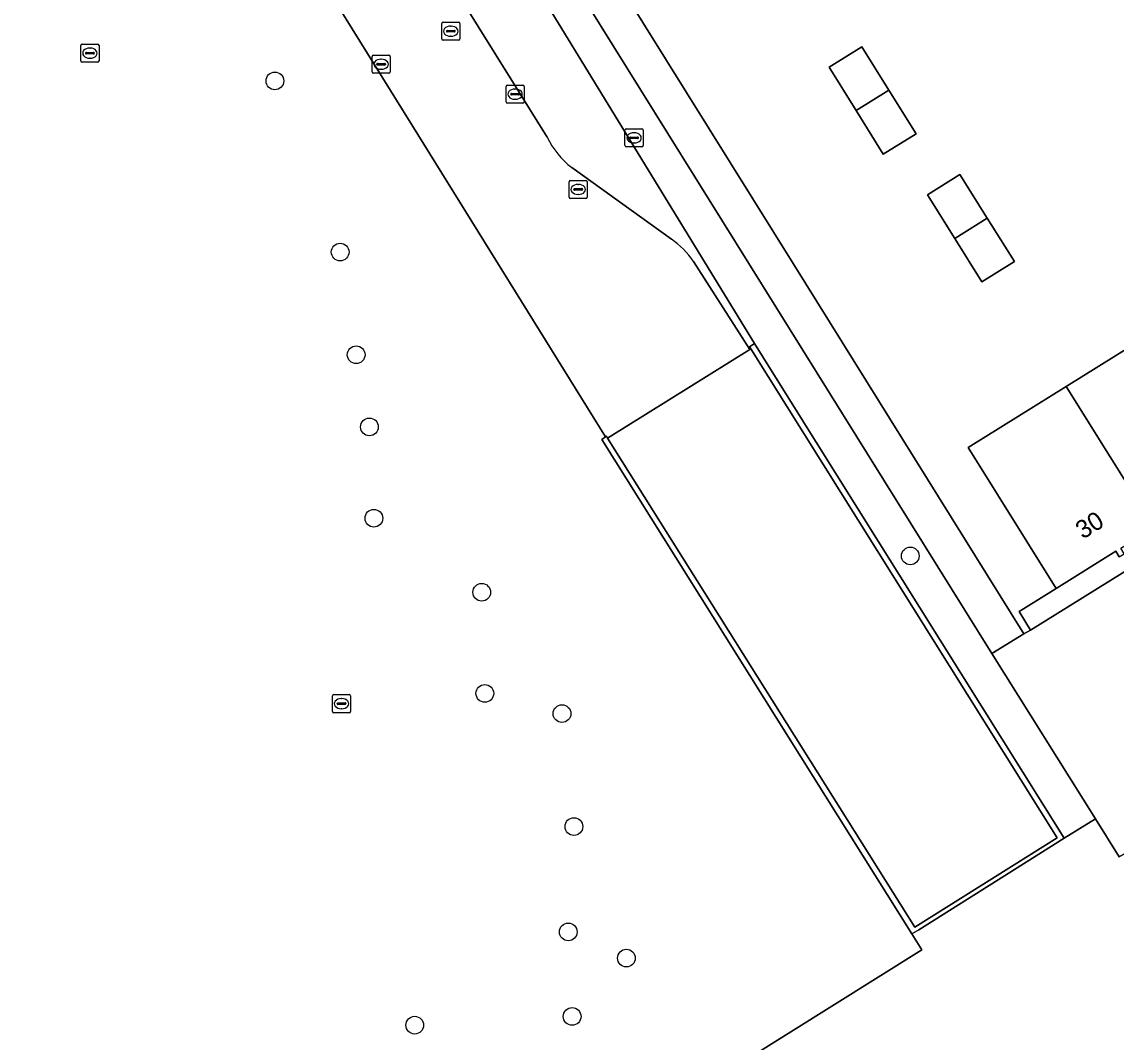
# Model space of a CAD drawing. Extents: x 159279 to 160377, y 384531 to 385888.
# Drawn here: x 159404.1 to 159464.5, y 385373.4 to 385429.8 of the extents above; entities that cross this region are included whole.
import ezdxf

# ---------------------------------------------------------------- set-up
doc = ezdxf.new("R2010")
doc.units = 0
for name, color, linetype in [('IMGEO_Boom', 7, 'Continuous'), ('IMGEO_Erf', 7, 'Continuous'), ('IMGEO_Groenvoorziening', 7, 'Continuous'), ('IMGEO_Kolk', 7, 'Continuous'), ('IMGEO_Muur', 7, 'Continuous'), ('IMGEO_Pand', 7, 'Continuous'), ('IMGEO_Pand_nummerreeks', 7, 'Continuous'), ('IMGEO_Rijbaan_lokaal_gesloten', 7, 'Continuous'), ('IMGEO_Rijbaan_lokaal_open', 7, 'Continuous'), ('IMGEO_Rioolput', 7, 'Continuous'), ('IMGEO_Voetgangersgebied_open', 7, 'Continuous')]:
    doc.layers.add(name, color=color, linetype=linetype)

msp = doc.modelspace()

# ---------------------------------------------------------------- linework, layer by layer
at = {"layer": 'IMGEO_Boom'}
for centre in [(159418.043, 385426.531), (159421.652, 385417.071), (159422.537, 385411.392), (159423.269, 385407.403), (159423.515, 385402.353), (159453.16, 385400.269), (159429.475, 385398.261), (159429.647, 385392.667), (159433.911, 385391.553), (159434.569, 385385.306), (159434.26, 385379.483), (159437.468, 385378.033), (159434.472, 385374.809), (159425.773, 385374.327)]:
    msp.add_circle(centre, 0.489, dxfattribs=at)
at = {"layer": 'IMGEO_Erf'}
for points in [[(159432.397, 385439.388), (159445.622, 385418.149), (159446.687, 385416.44), (159459.434, 385395.969), (159459.81, 385396.164), (159459.179, 385397.202), (159459.413, 385397.348), (159461.218, 385398.473), (159456.364, 385406.265), (159461.772, 385409.641), (159467.18, 385413.017), (159472.589, 385416.393), (159475.103, 385417.962), (159477.999, 385419.765), (159483.412, 385423.134), (159488.824, 385426.503), (159491.783, 385421.784), (159493.723, 385418.733), (159495.539, 385419.868), (159483.57, 385439.063)], [(159464.706, 385400.218), (159464.512, 385400.532), (159461.218, 385398.473), (159459.413, 385397.348), (159459.179, 385397.202), (159459.81, 385396.164), (159496.527, 385419.019)]]:
    msp.add_lwpolyline(points, dxfattribs=at)
for points in [[(159451.973, 385426.016), (159453.476, 385423.609), (159451.657, 385422.483), (159450.162, 385424.891), (159448.666, 385427.298), (159450.471, 385428.423)], [(159457.408, 385418.95), (159458.925, 385416.548), (159457.108, 385415.416), (159455.616, 385417.818), (159454.115, 385420.235), (159455.891, 385421.352)]]:
    msp.add_lwpolyline(points, close=True, dxfattribs=at)
at = {"layer": 'IMGEO_Groenvoorziening'}
for points in [[(159453.246, 385379.369), (159436.106, 385406.715), (159436.318, 385406.853), (159425.611, 385424.096), (159406.852, 385454.306)], [(159441.177, 385416.554), (159444.284, 385411.674), (159444.345, 385411.717), (159444.272, 385411.833), (159444.546, 385412.006), (159427.827, 385439.37), (159429.31, 385440.411)], [(159423.605, 385438.656), (159433.086, 385423.419)], [(159434.452, 385421.739), (159439.954, 385417.78)], [(159366.933, 385321.453), (159368.853, 385322.693), (159367.822, 385324.378), (159372.867, 385327.564), (159374.917, 385324.392), (159380.243, 385327.744), (159378.085, 385331.09), (159453.794, 385378.488), (159453.246, 385379.369)]]:
    msp.add_lwpolyline(points, dxfattribs=at)
msp.add_lwpolyline([(159429.31, 385440.411), (159427.827, 385439.37), (159444.546, 385412.006), (159446.812, 385408.385), (159461.661, 385384.66), (159463.396, 385385.729), (159457.667, 385394.881)], close=True, dxfattribs=at)
for centre, radius, start, end in [((159437.559, 385425.661), 5.003, 206.61733, 231.61146), ((159437.134, 385413.744), 4.924, 34.80227, 55.05735)]:
    msp.add_arc(centre, radius, start, end, dxfattribs=at)
at = {"layer": 'IMGEO_Kolk'}
for p, q in [((159423.414, 385427.027), (159423.414, 385427.879)), ((159423.489, 385427.953), (159424.341, 385427.953)), ((159423.902, 385427.733), (159423.927, 385427.733)), ((159424.415, 385427.879), (159424.415, 385427.027)), ((159423.673, 385427.447), (159423.673, 385427.459)), ((159424.111, 385427.41), (159423.713, 385427.41)), ((159423.716, 385427.496), (159424.114, 385427.496)), ((159423.925, 385427.173), (159423.9, 385427.173)), ((159424.157, 385427.459), (159424.157, 385427.447)), ((159424.341, 385426.953), (159423.489, 385426.953)), ((159430.817, 385425.374), (159430.817, 385426.226)), ((159430.892, 385426.3), (159431.744, 385426.3)), ((159431.076, 385425.794), (159431.076, 385425.806)), ((159431.119, 385425.843), (159431.517, 385425.843)), ((159431.305, 385426.08), (159431.33, 385426.08)), ((159431.56, 385425.806), (159431.56, 385425.794)), ((159431.818, 385426.226), (159431.818, 385425.374)), ((159431.744, 385425.3), (159430.892, 385425.3)), ((159431.514, 385425.757), (159431.116, 385425.757)), ((159431.328, 385425.52), (159431.303, 385425.52)), ((159437.392, 385422.958), (159437.392, 385423.81)), ((159437.467, 385423.884), (159438.319, 385423.884)), ((159437.651, 385423.378), (159437.651, 385423.39)), ((159437.694, 385423.427), (159438.092, 385423.427)), ((159437.88, 385423.664), (159437.905, 385423.664)), ((159438.135, 385423.39), (159438.135, 385423.378)), ((159438.393, 385423.81), (159438.393, 385422.958)), ((159438.319, 385422.884), (159437.467, 385422.884)), ((159438.089, 385423.341), (159437.691, 385423.341)), ((159437.903, 385423.104), (159437.878, 385423.104))]:
    msp.add_line(p, q, dxfattribs=at)
for points in [[(159423.414, 385427.027), (159423.414, 385427.879)], [(159423.489, 385427.953), (159424.341, 385427.953)], [(159424.415, 385427.879), (159424.415, 385427.027)], [(159424.341, 385426.953), (159423.489, 385426.953)], [(159430.817, 385425.374), (159430.817, 385426.226)], [(159430.892, 385426.3), (159431.744, 385426.3)], [(159431.818, 385426.226), (159431.818, 385425.374)], [(159431.744, 385425.3), (159430.892, 385425.3)], [(159437.392, 385422.958), (159437.392, 385423.81)], [(159437.467, 385423.884), (159438.319, 385423.884)], [(159438.393, 385423.81), (159438.393, 385422.958)], [(159438.319, 385422.884), (159437.467, 385422.884)]]:
    msp.add_lwpolyline(points, dxfattribs=at)
for centre, radius, start, end in [((159423.491, 385427.877), 0.0765, 91.55205, 178.44795), ((159423.491, 385427.877), 0.0765, 91.55205, 178.44795), ((159424.339, 385427.877), 0.0765, 1.55205, 88.44795), ((159424.339, 385427.877), 0.0765, 1.55205, 88.44795), ((159423.491, 385427.029), 0.0765, 181.55205, 268.44795), ((159423.491, 385427.029), 0.0765, 181.55205, 268.44795), ((159423.713, 385427.456), 0.0403, 85.87752, 175.75265), ((159423.71, 385427.446), 0.0366, 178.93798, 274.71019), ((159424.114, 385427.453), 0.043, 264.86636, 352.45326), ((159424.118, 385427.458), 0.0386, 1.73085, 96.63898), ((159424.339, 385427.029), 0.0765, 271.55205, 358.44795), ((159424.339, 385427.029), 0.0765, 271.55205, 358.44795), ((159430.894, 385426.224), 0.0765, 91.55205, 178.44795), ((159430.894, 385426.224), 0.0765, 91.55205, 178.44795), ((159431.116, 385425.803), 0.0403, 85.87752, 175.75265), ((159431.113, 385425.793), 0.0366, 178.93798, 274.71019), ((159431.517, 385425.8), 0.043, 264.86636, 352.45326), ((159431.521, 385425.805), 0.0386, 1.73085, 96.63898), ((159431.742, 385426.224), 0.0765, 1.55205, 88.44795), ((159431.742, 385426.224), 0.0765, 1.55205, 88.44795), ((159430.894, 385425.376), 0.0765, 181.55205, 268.44795), ((159430.894, 385425.376), 0.0765, 181.55205, 268.44795), ((159431.742, 385425.376), 0.0765, 271.55205, 358.44795), ((159431.742, 385425.376), 0.0765, 271.55205, 358.44795), ((159437.469, 385423.808), 0.0765, 91.55205, 178.44795), ((159437.469, 385423.808), 0.0765, 91.55205, 178.44795), ((159437.691, 385423.387), 0.0403, 85.87752, 175.75265), ((159437.688, 385423.377), 0.0366, 178.93798, 274.71019), ((159438.092, 385423.384), 0.043, 264.86636, 352.45326), ((159438.096, 385423.389), 0.0386, 1.73085, 96.63898), ((159438.317, 385423.808), 0.0765, 1.55205, 88.44795), ((159438.317, 385423.808), 0.0765, 1.55205, 88.44795), ((159437.469, 385422.96), 0.0765, 181.55205, 268.44795), ((159437.469, 385422.96), 0.0765, 181.55205, 268.44795), ((159438.317, 385422.96), 0.0765, 271.55205, 358.44795), ((159438.317, 385422.96), 0.0765, 271.55205, 358.44795)]:
    msp.add_arc(centre, radius, start, end, dxfattribs=at)
for centre, major_axis, ratio, start_param, end_param in [((159423.901, 385427.453), (-0.387, 0.002), 0.722429, 4.712389, 7.853982), ((159423.926, 385427.453), (-0.39, 0.002), 0.717154, 1.570796, 4.712389), ((159431.304, 385425.8), (-0.387, 0.002), 0.722429, 4.712389, 7.853982), ((159431.329, 385425.8), (-0.39, 0.002), 0.717154, 1.570796, 4.712389), ((159437.879, 385423.384), (-0.387, 0.002), 0.722429, 4.712389, 7.853982), ((159437.904, 385423.384), (-0.39, 0.002), 0.717154, 1.570796, 4.712389)]:
    msp.add_ellipse(centre, major_axis=major_axis, ratio=ratio, start_param=start_param, end_param=end_param, dxfattribs=at)
at = {"layer": 'IMGEO_Muur'}
msp.add_lwpolyline([(159457.508, 385382.049), (159461.661, 385384.66), (159446.812, 385408.385), (159444.546, 385412.006), (159444.272, 385411.833), (159444.345, 385411.717), (159461.275, 385384.678), (159453.415, 385379.751), (159436.429, 385406.782), (159436.365, 385406.883), (159436.318, 385406.853), (159436.106, 385406.715), (159453.246, 385379.369), (159453.622, 385379.606)], close=True, dxfattribs=at)
at = {"layer": 'IMGEO_Pand'}
for points in [[(159448.666, 385427.298), (159450.162, 385424.891), (159451.973, 385426.016), (159450.471, 385428.423)], [(159451.973, 385426.016), (159450.162, 385424.891), (159451.657, 385422.483), (159453.476, 385423.609)], [(159455.891, 385421.352), (159454.115, 385420.235), (159455.616, 385417.818), (159457.408, 385418.95)], [(159457.408, 385418.95), (159455.616, 385417.818), (159457.108, 385415.416), (159458.925, 385416.548)], [(159467.18, 385413.017), (159461.772, 385409.641), (159466.628, 385401.861), (159468.739, 385403.189), (159468.94, 385402.863), (159469.193, 385403.02), (159469.027, 385403.317), (159469.865, 385403.844), (159472.052, 385405.212)], [(159461.772, 385409.641), (159456.364, 385406.265), (159461.218, 385398.473), (159464.512, 385400.532), (159464.706, 385400.218), (159464.974, 385400.385), (159464.794, 385400.707), (159466.628, 385401.861)]]:
    msp.add_lwpolyline(points, close=True, dxfattribs=at)
at = {"layer": 'IMGEO_Rijbaan_lokaal_gesloten'}
msp.add_lwpolyline([(159444.345, 385411.717), (159444.284, 385411.674), (159436.429, 385406.782), (159453.415, 385379.751), (159461.275, 385384.678)], close=True, dxfattribs=at)
at = {"layer": 'IMGEO_Rijbaan_lokaal_open'}
for points in [[(159406.852, 385454.306), (159425.611, 385424.096), (159436.318, 385406.853), (159436.365, 385406.883), (159436.429, 385406.782), (159444.284, 385411.674), (159441.177, 385416.554)], [(159433.086, 385423.419), (159423.605, 385438.656)], [(159439.954, 385417.78), (159434.452, 385421.739)]]:
    msp.add_lwpolyline(points, dxfattribs=at)
for centre, radius, start, end in [((159437.559, 385425.661), 5.003, 206.61733, 231.61146), ((159437.134, 385413.744), 4.924, 34.80227, 55.05735)]:
    msp.add_arc(centre, radius, start, end, dxfattribs=at)
at = {"layer": 'IMGEO_Rioolput'}
for p, q in [((159427.266, 385428.853), (159427.266, 385429.705)), ((159427.341, 385429.779), (159428.193, 385429.779)), ((159427.754, 385429.559), (159427.779, 385429.559)), ((159428.267, 385429.705), (159428.267, 385428.853)), ((159427.525, 385429.273), (159427.525, 385429.285)), ((159427.963, 385429.236), (159427.565, 385429.236)), ((159427.568, 385429.322), (159427.966, 385429.322)), ((159427.777, 385428.999), (159427.752, 385428.999)), ((159428.009, 385429.285), (159428.009, 385429.273)), ((159407.325, 385427.639), (159407.325, 385428.491)), ((159407.4, 385428.565), (159408.252, 385428.565)), ((159407.813, 385428.345), (159407.838, 385428.345)), ((159408.326, 385428.491), (159408.326, 385427.639)), ((159428.193, 385428.779), (159427.341, 385428.779)), ((159407.584, 385428.059), (159407.584, 385428.071)), ((159408.022, 385428.022), (159407.624, 385428.022)), ((159407.627, 385428.108), (159408.025, 385428.108)), ((159407.836, 385427.785), (159407.811, 385427.785)), ((159408.068, 385428.071), (159408.068, 385428.059)), ((159408.252, 385427.565), (159407.4, 385427.565)), ((159434.306, 385420.106), (159434.306, 385420.958)), ((159434.381, 385421.032), (159435.233, 385421.032)), ((159435.307, 385420.958), (159435.307, 385420.106)), ((159434.565, 385420.526), (159434.565, 385420.538)), ((159435.003, 385420.489), (159434.605, 385420.489)), ((159434.608, 385420.575), (159435.006, 385420.575)), ((159434.794, 385420.812), (159434.819, 385420.812)), ((159435.049, 385420.538), (159435.049, 385420.526)), ((159435.233, 385420.032), (159434.381, 385420.032)), ((159434.817, 385420.252), (159434.792, 385420.252)), ((159421.229, 385391.674), (159421.229, 385392.526)), ((159421.304, 385392.6), (159422.156, 385392.6)), ((159422.23, 385392.526), (159422.23, 385391.674)), ((159421.488, 385392.094), (159421.488, 385392.106)), ((159421.926, 385392.057), (159421.528, 385392.057)), ((159421.531, 385392.143), (159421.929, 385392.143)), ((159421.717, 385392.38), (159421.742, 385392.38)), ((159421.972, 385392.106), (159421.972, 385392.094)), ((159422.156, 385391.6), (159421.304, 385391.6)), ((159421.74, 385391.82), (159421.715, 385391.82))]:
    msp.add_line(p, q, dxfattribs=at)
for points in [[(159427.266, 385428.853), (159427.266, 385429.705)], [(159427.341, 385429.779), (159428.193, 385429.779)], [(159428.267, 385429.705), (159428.267, 385428.853)], [(159407.325, 385427.639), (159407.325, 385428.491)], [(159407.4, 385428.565), (159408.252, 385428.565)], [(159408.326, 385428.491), (159408.326, 385427.639)], [(159428.193, 385428.779), (159427.341, 385428.779)], [(159408.252, 385427.565), (159407.4, 385427.565)], [(159434.306, 385420.106), (159434.306, 385420.958)], [(159434.381, 385421.032), (159435.233, 385421.032)], [(159435.307, 385420.958), (159435.307, 385420.106)], [(159435.233, 385420.032), (159434.381, 385420.032)], [(159421.229, 385391.674), (159421.229, 385392.526)], [(159421.304, 385392.6), (159422.156, 385392.6)], [(159422.23, 385392.526), (159422.23, 385391.674)], [(159422.156, 385391.6), (159421.304, 385391.6)]]:
    msp.add_lwpolyline(points, dxfattribs=at)
for centre, radius, start, end in [((159427.343, 385429.703), 0.0765, 91.55205, 178.44795), ((159427.343, 385429.703), 0.0765, 91.55205, 178.44795), ((159428.191, 385429.703), 0.0765, 1.55205, 88.44795), ((159428.191, 385429.703), 0.0765, 1.55205, 88.44795), ((159427.343, 385428.855), 0.0765, 181.55205, 268.44795), ((159427.343, 385428.855), 0.0765, 181.55205, 268.44795), ((159427.565, 385429.282), 0.0403, 85.87752, 175.75265), ((159427.562, 385429.272), 0.0366, 178.93798, 274.71019), ((159427.966, 385429.279), 0.043, 264.86636, 352.45326), ((159427.97, 385429.284), 0.0386, 1.73085, 96.63898), ((159428.191, 385428.855), 0.0765, 271.55205, 358.44795), ((159428.191, 385428.855), 0.0765, 271.55205, 358.44795), ((159407.402, 385428.489), 0.0765, 91.55205, 178.44795), ((159407.402, 385428.489), 0.0765, 91.55205, 178.44795), ((159408.25, 385428.489), 0.0765, 1.55205, 88.44795), ((159408.25, 385428.489), 0.0765, 1.55205, 88.44795), ((159407.402, 385427.641), 0.0765, 181.55205, 268.44795), ((159407.402, 385427.641), 0.0765, 181.55205, 268.44795), ((159407.624, 385428.068), 0.0403, 85.87752, 175.75265), ((159407.621, 385428.058), 0.0366, 178.93798, 274.71019), ((159408.025, 385428.065), 0.043, 264.86636, 352.45326), ((159408.029, 385428.07), 0.0386, 1.73085, 96.63898), ((159408.25, 385427.641), 0.0765, 271.55205, 358.44795), ((159408.25, 385427.641), 0.0765, 271.55205, 358.44795), ((159434.383, 385420.956), 0.0765, 91.55205, 178.44795), ((159434.383, 385420.956), 0.0765, 91.55205, 178.44795), ((159435.231, 385420.956), 0.0765, 1.55205, 88.44795), ((159435.231, 385420.956), 0.0765, 1.55205, 88.44795), ((159434.605, 385420.535), 0.0403, 85.87752, 175.75265), ((159434.602, 385420.525), 0.0366, 178.93798, 274.71019), ((159435.006, 385420.532), 0.043, 264.86636, 352.45326), ((159435.01, 385420.537), 0.0386, 1.73085, 96.63898), ((159434.383, 385420.108), 0.0765, 181.55205, 268.44795), ((159434.383, 385420.108), 0.0765, 181.55205, 268.44795), ((159435.231, 385420.108), 0.0765, 271.55205, 358.44795), ((159435.231, 385420.108), 0.0765, 271.55205, 358.44795), ((159421.306, 385392.524), 0.0765, 91.55205, 178.44795), ((159421.306, 385392.524), 0.0765, 91.55205, 178.44795), ((159422.154, 385392.524), 0.0765, 1.55205, 88.44795), ((159422.154, 385392.524), 0.0765, 1.55205, 88.44795), ((159421.528, 385392.103), 0.0403, 85.87752, 175.75265), ((159421.525, 385392.093), 0.0366, 178.93798, 274.71019), ((159421.929, 385392.1), 0.043, 264.86636, 352.45326), ((159421.933, 385392.105), 0.0386, 1.73085, 96.63898), ((159421.306, 385391.676), 0.0765, 181.55205, 268.44795), ((159421.306, 385391.676), 0.0765, 181.55205, 268.44795), ((159422.154, 385391.676), 0.0765, 271.55205, 358.44795), ((159422.154, 385391.676), 0.0765, 271.55205, 358.44795)]:
    msp.add_arc(centre, radius, start, end, dxfattribs=at)
for centre, major_axis, ratio, start_param, end_param in [((159427.753, 385429.279), (-0.387, 0.002), 0.722429, 4.712389, 7.853982), ((159427.778, 385429.279), (-0.39, 0.002), 0.717154, 1.570796, 4.712389), ((159407.812, 385428.065), (-0.387, 0.002), 0.722429, 4.712389, 7.853982), ((159407.837, 385428.065), (-0.39, 0.002), 0.717154, 1.570796, 4.712389), ((159434.793, 385420.532), (-0.387, 0.002), 0.722429, 4.712389, 7.853982), ((159434.818, 385420.532), (-0.39, 0.002), 0.717154, 1.570796, 4.712389), ((159421.716, 385392.1), (-0.387, 0.002), 0.722429, 4.712389, 7.853982), ((159421.741, 385392.1), (-0.39, 0.002), 0.717154, 1.570796, 4.712389)]:
    msp.add_ellipse(centre, major_axis=major_axis, ratio=ratio, start_param=start_param, end_param=end_param, dxfattribs=at)
at = {"layer": 'IMGEO_Voetgangersgebied_open'}
msp.add_lwpolyline([(159432.397, 385439.388), (159432.186, 385439.727), (159431.117, 385441.443), (159430.43, 385442.533), (159427.756, 385446.597), (159427.621, 385446.775), (159425.983, 385445.744), (159426.111, 385445.547), (159429.31, 385440.411), (159457.667, 385394.881), (159459.434, 385395.969), (159446.687, 385416.44), (159445.622, 385418.149)], close=True, dxfattribs=at)
for points in [[(159515.214, 385430.074), (159498.421, 385419.623), (159498.164, 385420.032), (159496.527, 385419.019), (159459.81, 385396.164), (159459.434, 385395.969), (159457.667, 385394.881), (159463.396, 385385.729), (159464.704, 385383.64), (159467.362, 385385.157), (159473.614, 385375.297), (159481.223, 385380.079), (159486.183, 385383.185), (159479.206, 385394.415), (159480.107, 385394.975), (159481.742, 385395.994), (159483.001, 385396.779), (159484.628, 385397.793), (159521.522, 385420.783)], [(159389.39, 385321.78), (159429.394, 385258.118), (159424.986, 385255.303), (159426.009, 385253.608), (159497.859, 385298.653), (159506.85, 385304.364), (159515.25, 385309.623), (159513.073, 385313.056), (159512.632, 385312.774), (159509.325, 385318.031), (159509.752, 385318.295), (159473.614, 385375.297), (159467.362, 385385.157), (159464.704, 385383.64), (159463.396, 385385.729), (159461.661, 385384.66), (159457.508, 385382.049), (159453.622, 385379.606), (159453.246, 385379.369), (159453.794, 385378.488), (159378.085, 385331.09)]]:
    msp.add_lwpolyline(points, dxfattribs=at)

# ---------------------------------------------------------------- texts
at = {"layer": 'IMGEO_Pand_nummerreeks'}
msp.add_text('30', height=1, rotation=32.01115, dxfattribs=at).set_placement((159462.695, 385401.165))

doc.saveas('drawing.dxf')
